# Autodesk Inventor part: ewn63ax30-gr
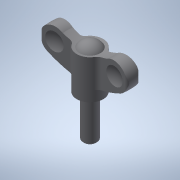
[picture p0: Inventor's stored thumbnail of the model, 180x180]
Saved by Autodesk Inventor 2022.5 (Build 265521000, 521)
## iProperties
Created: 2017-05
Part Number: ewn63ax30-gr
Material: 一般
Document SubType Name: Modeling
Designer: imaocorp
Density: 1 g/cm^3
Appearance: 既定
Author: imaocorp
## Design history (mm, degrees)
node "ewn63ax30-gr.x_t1"
node "ewn63ax30-gr"
node "Base1"
